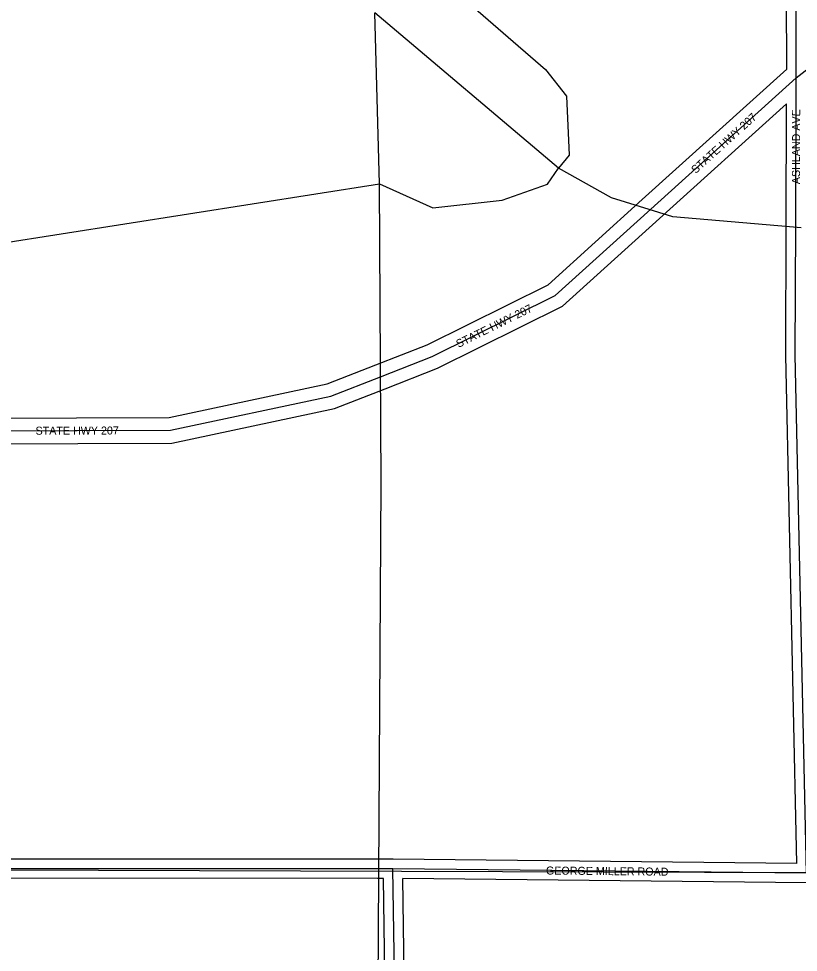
# Model space of a CAD drawing. Extents: x 418523 to 616617, y 1878279 to 2196743.
# Drawn here: x 497620 to 500055, y 1954823 to 1957739 of the extents above; entities that cross this region are included whole.
import ezdxf

# ---------------------------------------------------------------- set-up
doc = ezdxf.new("R2010")
doc.units = 0
for name, color, linetype in [('Level 1', 7, 'Continuous'), ('Level 22', 7, 'Continuous'), ('Level 23', 7, 'Continuous'), ('Level 31', 7, 'Continuous'), ('Level 32', 7, 'Continuous'), ('Level 34', 7, 'Continuous'), ('Level 5', 7, 'Continuous'), ('Level 7', 7, 'Continuous')]:
    doc.layers.add(name, color=color, linetype=linetype)

msp = doc.modelspace()

# ---------------------------------------------------------------- linework, layer by layer
at = {"layer": 'Level 1'}
msp.add_line((500077.56, 1955070.604), (497503.83, 1955079.028), dxfattribs=at)
at = {"layer": 'Level 22'}
msp.add_line((499594.539, 1957143.901), (500048.657, 1957554.362), dxfattribs=at)
for points in [[(500048.657, 1957554.362), (500165.868, 1957645.871), (501220.408, 1958767.306), (501220.653, 1958825.49)], [(498750.081, 1956620.198), (498911.623, 1956683.511), (499295.93, 1956873.884), (499594.539, 1957143.901)], [(497509.735, 1956451.334), (498093.802, 1956453.183), (498594.582, 1956559.406), (498750.081, 1956620.198)]]:
    msp.add_lwpolyline(points, dxfattribs=at)
at = {"layer": 'Level 23'}
for p, q in [((499567.717, 1957173.576), (500018.593, 1957581.106)), ((499621.361, 1957114.226), (500018.369, 1957473.065))]:
    msp.add_line(p, q, dxfattribs=at)
for points in [[(498735.485, 1956657.441), (498895.416, 1956720.123), (499273.209, 1956907.269), (499567.71, 1957173.571)], [(498764.679, 1956582.956), (498927.83, 1956646.901), (499318.65, 1956840.498), (499621.367, 1957114.232)], [(497509.907, 1956491.336), (498089.544, 1956493.171), (498583.072, 1956597.856), (498735.516, 1956657.453)], [(497509.563, 1956411.33), (497509.944, 1956411.334), (498098.06, 1956413.196), (498606.091, 1956520.956), (498764.647, 1956582.943)]]:
    msp.add_lwpolyline(points, dxfattribs=at)
at = {"layer": 'Level 31'}
for p, q in [((500048.657, 1957554.362), (500045.423, 1958888.281)), ((500047.038, 1957097.249), (500048.657, 1957554.362)), ((498740.975, 1955083.411), (497503.851, 1955083.997)), ((498788.914, 1955083.206), (498740.975, 1955083.411)), ((500080.989, 1955070.066), (498788.914, 1955083.206)), ((498806.336, 1953810.321), (498788.914, 1955083.206))]:
    msp.add_line(p, q, dxfattribs=at)
msp.add_lwpolyline([(500080.989, 1955070.066), (500045.618, 1956687.411), (500047.038, 1957097.249)], dxfattribs=at)
at = {"layer": 'Level 32'}
for p, q in [((500018.593, 1957581.106), (500015.469, 1958869.805)), ((500017.038, 1957097.355), (500018.37, 1957473.065)), ((498740.99, 1955113.411), (497503.98, 1955113.998)), ((498789.043, 1955113.206), (498741.104, 1955113.411)), ((500050.319, 1955100.379), (498789.22, 1955113.205)), ((498740.961, 1955053.411), (497503.722, 1955053.996)), ((498759.32, 1955053.331), (498740.848, 1955053.411)), ((498776.339, 1953809.911), (498759.32, 1955053.331)), ((498835.951, 1953838.733), (498819.333, 1955052.894)), ((500080.685, 1955040.066), (498819.334, 1955052.893))]:
    msp.add_line(p, q, dxfattribs=at)
msp.add_lwpolyline([(500050.319, 1955100.379), (500015.616, 1956687.134), (500017.037, 1957097.352)], dxfattribs=at)
at = {"layer": 'Level 5'}
for p, q in [((498746.857, 1957223.191), (498731.876, 1957756.753)), ((499305.559, 1957271.42), (498731.876, 1957756.753)), ((498752.195, 1956289.49), (498746.857, 1957223.191))]:
    msp.add_line(p, q, dxfattribs=at)
for points in [[(500063.58, 1957085.566), (499663.53, 1957120.221), (499471.985, 1957179.16), (499305.559, 1957271.42)], [(497908.346, 1953099.346), (498733.774, 1953138.387), (498752.195, 1956289.49)]]:
    msp.add_lwpolyline(points, dxfattribs=at)
at = {"layer": 'Level 7'}
msp.add_line((497512.22, 1957028.746), (498746.857, 1957223.191), dxfattribs=at)
for points in [[(500170.155, 1961728.624), (499936.968, 1961804.402), (499211.542, 1961756.701), (499002.968, 1961707.368), (498777.495, 1961583.041), (498660.395, 1961458.357), (498660.265, 1961416.676), (498325.048, 1960867.56), (498316.479, 1960792.557), (498291.409, 1960775.956), (498232.53, 1960609.422), (498223.773, 1960484.409), (498198.693, 1960459.468), (498230.512, 1959984.198), (498271.736, 1959842.345), (498428.946, 1959475.029), (498495.48, 1959424.808), (498552.945, 1959149.513), (498525.4, 1958357.654), (498657.998, 1958107.141), (499264.852, 1957579.996), (499331.285, 1957496.396), (499339.029, 1957313.001), (499305.559, 1957271.42)], [(498746.857, 1957223.191), (498913.352, 1957147.611), (499130.166, 1957171.935), (499272.049, 1957221.498), (499305.559, 1957271.42)]]:
    msp.add_lwpolyline(points, dxfattribs=at)

# ---------------------------------------------------------------- texts
at = {"layer": 'Level 34'}
for s, height, rotation, p in [('STATE HWY 207', 25, 42.108317, (499734.179, 1957253.27)), ('ASHLAND AVE', 24.99916, 89.795886, (500059.975, 1957221.834)), ('STATE HWY 207', 25, 26.351383, (498993.61, 1956710.177)), ('STATE HWY 207', 25, 0.180642, (497672.636, 1956439.351)), ('GEORGE MILLER ROAD', 25, 359.416567, (499266.643, 1955065.848))]:
    msp.add_text(s, height=height, rotation=rotation, dxfattribs=at).set_placement(p)

doc.saveas('drawing.dxf')
